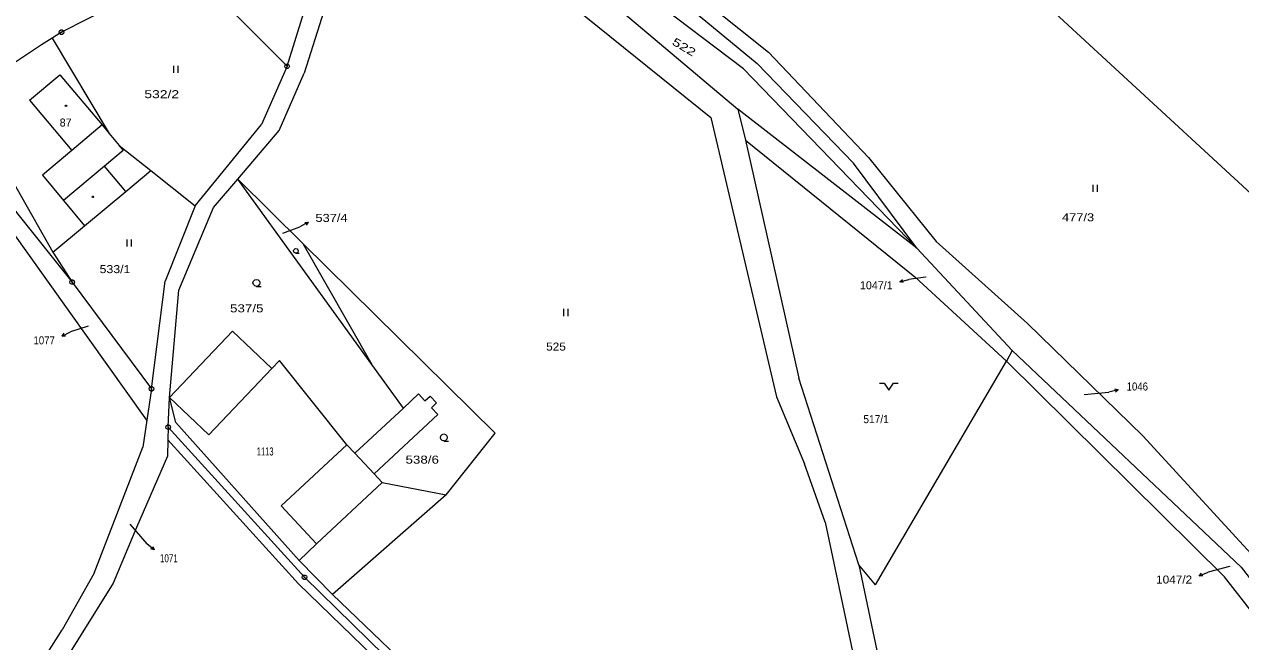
# Model space of a CAD drawing. Extents: x -687390 to -684106, y -954833 to -951648.
# Drawn here: x -686934.3 to -686675.9, y -953016.7 to -952885.7 of the extents above; entities that cross this region are included whole.
import ezdxf
from ezdxf.enums import TextEntityAlignment as Align

# ---------------------------------------------------------------- set-up
doc = ezdxf.new("R2010")
doc.units = 0
doc.header["$LTSCALE"] = 0.68
for name, color, linetype, lineweight in [('1', 7, 'Continuous', 13), ('3', 7, 'Continuous', 13), ('4', 7, 'Continuous', 13), ('5', 7, 'Continuous', 13), ('7', 7, 'Continuous', 13), ('8', 7, 'Continuous', 13)]:
    doc.layers.add(name, color=color, linetype=linetype, lineweight=lineweight)
doc.layers.add('2', color=7, linetype='Continuous')

msp = doc.modelspace()

# ---------------------------------------------------------------- linework, layer by layer
at = {"layer": '1'}
for p, q in [((-686781.53, -952895.13), (-686832.15, -952856.7)), ((-686672.7, -952922.52), (-686738.23, -952862.13)), ((-686878.46, -952894.57), (-686870.09, -952867.67)), ((-686866.64, -952870.3), (-686874.83, -952896.01)), ((-686928.34, -952888.57), (-686916.22, -952908.85)), ((-686778.58, -952894), (-686758.14, -952915.15)), ((-686880.14, -952908.22), (-686874.83, -952896.01)), ((-686898.01, -952924.16), (-686883.9, -952906.93)), ((-686788.47, -952905.46), (-686774.47, -952964.74)), ((-686916.22, -952908.85), (-686914.13, -952911.36)), ((-686781.1, -952910.23), (-686745.07, -952939.23)), ((-686781.1, -952910.23), (-686769.73, -952960.76)), ((-686744.67, -952933.19), (-686758.14, -952915.15)), ((-686888.94, -952918.51), (-686875.1, -952932.16)), ((-686898.01, -952924.16), (-686904.36, -952940.21)), ((-686928.21, -952934), (-686921.5, -952928.41)), ((-686908.24, -952969.66), (-686937.22, -952929.1)), ((-686875.1, -952932.16), (-686860.43, -952957.87)), ((-686875.1, -952932.16), (-686834.27, -952972.43)), ((-686907.26, -952963.03), (-686904.36, -952940.21)), ((-686725.64, -952957.15), (-686745.07, -952939.23)), ((-686903.41, -952964.85), (-686890.04, -952950.78)), ((-686890.04, -952950.78), (-686881.71, -952958.71)), ((-686721.14, -952949.16), (-686696.66, -952973)), ((-686724.45, -952954.91), (-686725.64, -952957.15)), ((-686880.08, -952956.99), (-686881.71, -952958.71)), ((-686865.77, -952974.89), (-686880.08, -952956.99)), ((-686753.48, -953004.6), (-686725.64, -952957.15)), ((-686757.01, -953000.39), (-686769.73, -952960.76)), ((-686907.26, -952963.03), (-686908.24, -952969.66)), ((-686903.71, -952971.16), (-686903.41, -952964.85)), ((-686774.47, -952964.74), (-686768.56, -952978.93)), ((-686908.24, -952969.66), (-686909.07, -952975.38)), ((-686903.71, -952971.16), (-686903.82, -952973.82)), ((-686903.82, -952973.82), (-686903.84, -952977.29)), ((-686903.82, -952973.82), (-686876.02, -953004.42)), ((-686864.07, -952976.71), (-686865.77, -952974.89)), ((-686844.69, -952985.51), (-686834.27, -952972.43)), ((-686670.54, -953001.44), (-686696.66, -952973)), ((-686919.43, -953002.13), (-686909.07, -952975.38)), ((-686764.18, -952991.34), (-686768.56, -952978.93)), ((-686764.18, -952991.34), (-686757.06, -953024.89)), ((-686875.86, -952999.48), (-686868.78, -953006.67)), ((-686753.48, -953004.6), (-686757.01, -953000.39)), ((-686919.43, -953002.13), (-686926.22, -953014.19)), ((-686940.23, -953036.04), (-686926.22, -953014.19))]:
    msp.add_line(p, q, dxfattribs=at)
for points in [[(-686838.22, -952831.93), (-686822.92, -952853.47), (-686807.34, -952866.66), (-686776.21, -952891.55)], [(-686841.02, -952834.1), (-686825.81, -952854.97), (-686778.58, -952894)], [(-686851, -952843.7), (-686832.64, -952861.61), (-686782.67, -952903.64), (-686781.1, -952910.23)], [(-686859.05, -952848.49), (-686849.89, -952855.92), (-686788.47, -952905.46)], [(-686899.83, -952873.14), (-686878.46, -952894.57), (-686883.9, -952906.93)], [(-686910.31, -952879.12), (-686920.81, -952884.49), (-686926.37, -952887.33)], [(-686926.37, -952887.33), (-686928.34, -952888.57), (-686930.65, -952890.02)], [(-686930.65, -952890.02), (-686937.22, -952894.39), (-686947.05, -952900.93)], [(-686776.21, -952891.55), (-686754.92, -952913.96), (-686740.55, -952931.75), (-686721.14, -952949.16)], [(-686947.05, -952900.93), (-686949.85, -952896.26), (-686955.03, -952899), (-686935.91, -952925.58), (-686924.11, -952940.37), (-686907.26, -952963.03)], [(-686781.53, -952895.13), (-686744.67, -952933.19), (-686782.67, -952903.64)], [(-686947.05, -952900.93), (-686928.21, -952934), (-686924.11, -952940.37)], [(-686894.1, -952924.53), (-686888.94, -952918.51), (-686880.14, -952908.22)], [(-686914.13, -952911.36), (-686907.42, -952916.68), (-686898.01, -952924.16)], [(-686921.5, -952928.41), (-686912.74, -952921.12), (-686907.42, -952916.68)], [(-686853.75, -952967.1), (-686860.43, -952957.87), (-686888.94, -952918.51)], [(-686875.86, -952999.48), (-686902.08, -952970.19), (-686903.41, -952964.85), (-686901.46, -952942.07), (-686894.1, -952924.53)], [(-686744.67, -952933.19), (-686724.45, -952954.91), (-686675.78, -953000.89), (-686652.38, -953031), (-686618.65, -953085.9), (-686604.76, -953115.49), (-686593.43, -953134.24)], [(-686655.57, -953033.26), (-686679.35, -953002.91), (-686725.64, -952957.15)], [(-686864.07, -952976.71), (-686853.75, -952967.1), (-686850.53, -952964.1)], [(-686850.53, -952964.1), (-686849.17, -952965.57), (-686848.07, -952964.55), (-686846.7, -952966.01), (-686847.8, -952967.03), (-686846.44, -952968.5), (-686859.97, -952981.1), (-686858.27, -952982.94)], [(-686903.71, -952971.16), (-686874.76, -953003.02), (-686833.89, -953042.95), (-686787.58, -953076.97), (-686748.81, -953115.73), (-686749.19, -953118.31), (-686744.38, -953124.12), (-686735.23, -953139.57), (-686726.05, -953159.19), (-686709.09, -953210.04), (-686703.22, -953229.26), (-686695.71, -953262.97)], [(-686903.84, -952977.29), (-686910.44, -952992.44), (-686915.44, -953004.28), (-686929.03, -953026.05)], [(-686858.27, -952982.94), (-686844.69, -952985.51), (-686868.78, -953006.67)], [(-686757.01, -953000.39), (-686749.02, -953038.47), (-686745.94, -953060.65)], [(-686876.02, -953004.42), (-686835.02, -953044.1), (-686788.37, -953078.75), (-686749.19, -953118.31)], [(-686868.78, -953006.67), (-686832.75, -953041.23), (-686786.65, -953075.62)]]:
    msp.add_lwpolyline(points, dxfattribs=at)
at = {"layer": '3'}
for p, q in [((-686902.61, -952894.47), (-686902.61, -952895.97)), ((-686901.61, -952895.97), (-686901.61, -952894.47)), ((-686707.26, -952919.75), (-686707.26, -952921.25)), ((-686706.26, -952921.25), (-686706.26, -952919.75)), ((-686912.49, -952931.32), (-686912.49, -952932.82)), ((-686911.49, -952932.82), (-686911.49, -952931.32)), ((-686819.72, -952946.07), (-686819.72, -952947.57)), ((-686818.72, -952947.57), (-686818.72, -952946.07))]:
    msp.add_line(p, q, dxfattribs=at)
for points in [[(-686876.57, -952934.24), (-686876.825, -952934.173), (-686877.006, -952933.992), (-686877.072, -952933.744), (-686877.006, -952933.496), (-686876.825, -952933.315), (-686876.577, -952933.248), (-686876.329, -952933.315), (-686876.148, -952933.496), (-686876.081, -952933.751), (-686876.148, -952934.006), (-686876.329, -952934.186), (-686876.583, -952934.253), (-686875.913, -952934.253)], [(-686884.95, -952941.28), (-686885.33, -952941.18), (-686885.6, -952940.91), (-686885.7, -952940.54), (-686885.6, -952940.17), (-686885.33, -952939.9), (-686884.96, -952939.8), (-686884.59, -952939.9), (-686884.32, -952940.17), (-686884.22, -952940.55), (-686884.32, -952940.93), (-686884.59, -952941.2), (-686884.97, -952941.3), (-686883.97, -952941.3)], [(-686752.63, -952961.81), (-686751.63, -952961.81), (-686750.63, -952963.31), (-686749.63, -952961.81), (-686748.63, -952961.81)], [(-686845.15, -952974.09), (-686845.53, -952973.99), (-686845.8, -952973.72), (-686845.9, -952973.35), (-686845.8, -952972.98), (-686845.53, -952972.71), (-686845.16, -952972.61), (-686844.79, -952972.71), (-686844.52, -952972.98), (-686844.42, -952973.36), (-686844.52, -952973.74), (-686844.79, -952974.01), (-686845.17, -952974.11), (-686844.17, -952974.11)]]:
    msp.add_lwpolyline(points, dxfattribs=at)
at = {"layer": '4'}
for p, q in [((-686933.17, -952901.73), (-686926.7, -952896.37)), ((-686917.75, -952907.03), (-686924.19, -952912.44)), ((-686913.25, -952912.42), (-686917.22, -952915.74)), ((-686914.13, -952911.36), (-686913.25, -952912.42)), ((-686917.22, -952915.74), (-686925.97, -952923.05)), ((-686912.74, -952921.12), (-686917.22, -952915.74)), ((-686881.71, -952958.71), (-686895.07, -952972.77)), ((-686903.41, -952964.85), (-686895.07, -952972.77)), ((-686879.7, -952987.86), (-686865.77, -952974.89)), ((-686864.07, -952976.71), (-686859.97, -952981.1)), ((-686872.19, -952995.91), (-686875.86, -952999.48))]:
    msp.add_line(p, q, dxfattribs=at)
for points in [[(-686926.7, -952896.37), (-686917.75, -952907.03), (-686916.22, -952908.85)], [(-686933.17, -952901.73), (-686924.19, -952912.44), (-686930.45, -952917.7)], [(-686930.45, -952917.7), (-686925.97, -952923.05), (-686921.5, -952928.41)], [(-686858.27, -952982.94), (-686872.19, -952995.91), (-686879.7, -952987.86)]]:
    msp.add_lwpolyline(points, dxfattribs=at)
at = {"layer": '5'}
for points in [[(-686925.33, -952902.84), (-686925.24, -952902.99), (-686925.33, -952903.14), (-686925.51, -952903.14), (-686925.6, -952902.99), (-686925.51, -952902.84)], [(-686919.62, -952922.11), (-686919.53, -952922.26), (-686919.62, -952922.41), (-686919.8, -952922.41), (-686919.89, -952922.26), (-686919.8, -952922.11)]]:
    msp.add_lwpolyline(points, close=True, dxfattribs=at)
at = {"layer": '7'}
for p, q in [((-686873.956, -952927.687), (-686875.72, -952928.65)), ((-686879.35, -952930), (-686875.72, -952928.65)), ((-686748.296, -952940.35), (-686746.36, -952939.81)), ((-686742.85, -952939.35), (-686746.36, -952939.81)), ((-686926.261, -952951.833), (-686924.46, -952950.94)), ((-686920.69, -952949.7), (-686924.46, -952950.94)), ((-686709.16, -952964.24), (-686703.88, -952963.7)), ((-686701.93, -952963.213), (-686703.88, -952963.7)), ((-686911.89, -952991.74), (-686908.23, -952995.89)), ((-686906.701, -952997.195), (-686908.23, -952995.89)), ((-686678.24, -953000.75), (-686682.82, -953001.92)), ((-686684.679, -953002.685), (-686682.82, -953001.92))]:
    msp.add_line(p, q, dxfattribs=at)
for points in [[(-686874.704, -952927.714), (-686873.956, -952927.687), (-686874.383, -952928.302)], [(-686747.561, -952940.493), (-686748.296, -952940.35), (-686747.741, -952939.848)], [(-686925.512, -952951.835), (-686926.261, -952951.833), (-686925.809, -952951.235)], [(-686702.661, -952963.05), (-686701.93, -952963.213), (-686702.499, -952963.701)], [(-686906.993, -952996.505), (-686906.701, -952997.195), (-686907.428, -952997.015)], [(-686683.932, -953002.74), (-686684.679, -953002.685), (-686684.187, -953002.12)]]:
    msp.add_lwpolyline(points, dxfattribs=at)
at = {"layer": '8'}
for p, q in [((-686926.49, -952887.33), (-686926.25, -952887.33)), ((-686878.58, -952894.57), (-686878.34, -952894.57)), ((-686924.23, -952940.37), (-686923.99, -952940.37)), ((-686907.38, -952963.03), (-686907.14, -952963.03)), ((-686903.83, -952971.16), (-686903.59, -952971.16)), ((-686874.88, -953003.02), (-686874.64, -953003.02))]:
    msp.add_line(p, q, dxfattribs=at)
for points in [[(-686926.22, -952886.85), (-686925.97, -952887.03), (-686925.87, -952887.32), (-686925.97, -952887.61), (-686926.22, -952887.79), (-686926.53, -952887.79), (-686926.78, -952887.61), (-686926.88, -952887.32), (-686926.78, -952887.03), (-686926.53, -952886.85)], [(-686878.31, -952894.09), (-686878.06, -952894.27), (-686877.96, -952894.56), (-686878.06, -952894.85), (-686878.31, -952895.03), (-686878.62, -952895.03), (-686878.87, -952894.85), (-686878.97, -952894.56), (-686878.87, -952894.27), (-686878.62, -952894.09)], [(-686923.96, -952939.89), (-686923.71, -952940.07), (-686923.61, -952940.36), (-686923.71, -952940.65), (-686923.96, -952940.83), (-686924.27, -952940.83), (-686924.52, -952940.65), (-686924.62, -952940.36), (-686924.52, -952940.07), (-686924.27, -952939.89)], [(-686907.11, -952962.55), (-686906.86, -952962.73), (-686906.76, -952963.02), (-686906.86, -952963.31), (-686907.11, -952963.49), (-686907.42, -952963.49), (-686907.67, -952963.31), (-686907.77, -952963.02), (-686907.67, -952962.73), (-686907.42, -952962.55)], [(-686903.56, -952970.68), (-686903.31, -952970.86), (-686903.21, -952971.15), (-686903.31, -952971.44), (-686903.56, -952971.62), (-686903.87, -952971.62), (-686904.12, -952971.44), (-686904.22, -952971.15), (-686904.12, -952970.86), (-686903.87, -952970.68)], [(-686874.61, -953002.54), (-686874.36, -953002.72), (-686874.26, -953003.01), (-686874.36, -953003.3), (-686874.61, -953003.48), (-686874.92, -953003.48), (-686875.17, -953003.3), (-686875.27, -953003.01), (-686875.17, -953002.72), (-686874.92, -953002.54)]]:
    msp.add_lwpolyline(points, close=True, dxfattribs=at)

# ---------------------------------------------------------------- texts
at = {"layer": '2', "width": 1.4}
msp.add_text('522', height=1.7, rotation=329.279, dxfattribs=at).set_placement((-686796.842, -952889.853))
at = {"layer": '2'}
for s, height, width, p in [('532/2', 1.7, 1.3, (-686908.785, -952901.34)), ('477/3', 1.7, 1.2, (-686713.835, -952927.47)), ('537/4', 0.1, 1.2, (-686879.322, -952930)), ('533/1', 1.7, 1.15, (-686918.285, -952938.47)), ('537/5', 1.7, 1.25, (-686890.585, -952946.79)), ('1077', 0.1, 0.9, (-686920.644, -952949.7)), ('525', 1.7, 1.1, (-686823.415, -952954.91)), ('1046', 0.1, 0.9, (-686709.114, -952964.24)), ('517/1', 1.7, 0.95, (-686756.035, -952970.31)), ('1113', 1.7, 0.65, (-686884.905, -952977.17)), ('538/6', 1.7, 1.25, (-686853.305, -952978.9)), ('1071', 0.1, 0.75, (-686911.844, -952991.74)), ('1047/2', 0.1, 1.1, (-686678.194, -953000.75))]:
    msp.add_text(s, height=height, dxfattribs=dict(at, width=width)).set_placement(p)
for s, height, p in [('87', 1.7, (-686926.765, -952907.36)), ('1047/1', 0.1, (-686742.804, -952939.35))]:
    msp.add_text(s, height=height, dxfattribs=at).set_placement(p)
at = {"layer": '7'}
for s, width, p in [('537/4', 1.2, (-686872.435, -952927.6)), ('1046', 0.9, (-686700.115, -952963.38)), ('1071', 0.75, (-686905.465, -952999.84))]:
    msp.add_text(s, height=1.7, dxfattribs=dict(at, width=width)).set_placement(p)
msp.add_text('1047/1', height=1.7, dxfattribs=at).set_placement((-686749.806, -952941.9), align=Align.RIGHT)
for s, width, p in [('1077', 0.9, (-686927.786, -952953.58)), ('1047/2', 1.1, (-686686.196, -953004.35))]:
    msp.add_text(s, height=1.7, dxfattribs=dict(at, width=width)).set_placement(p, align=Align.RIGHT)

doc.saveas('drawing.dxf')
